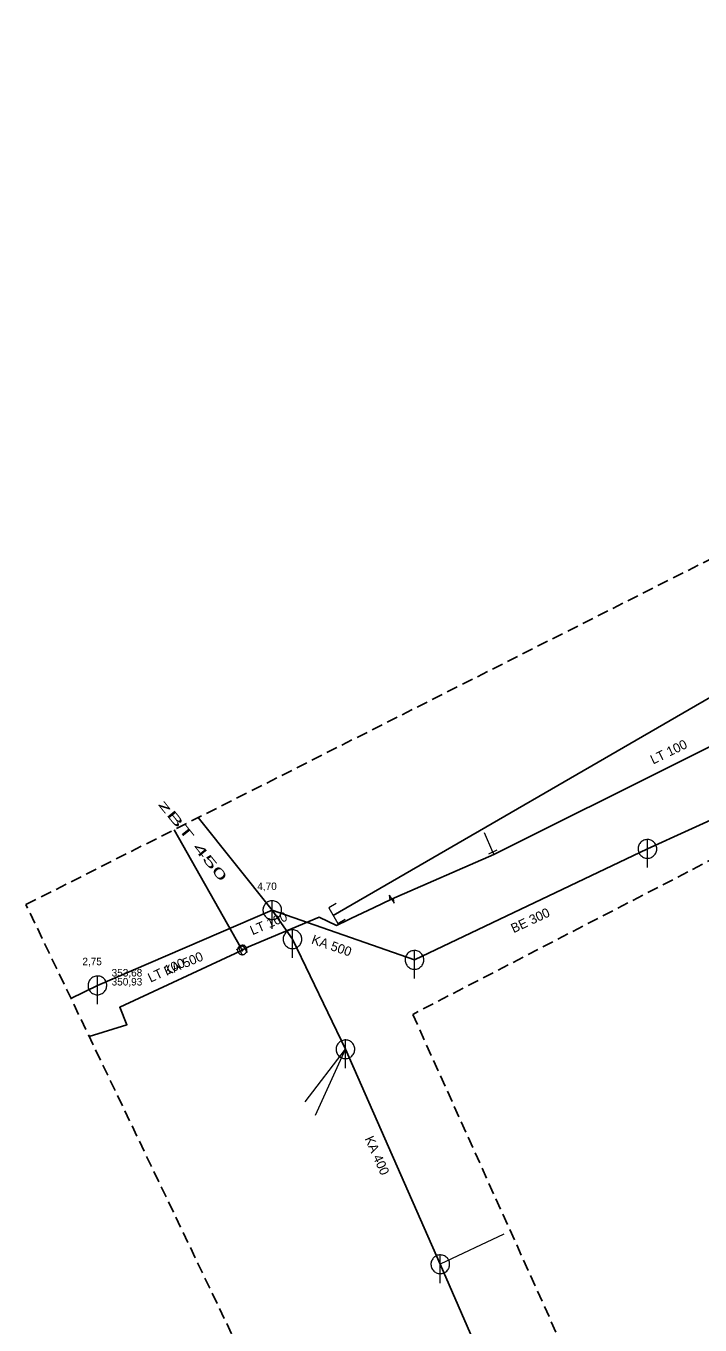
# Model space of a CAD drawing. Extents: x -688691 to -688449, y -974248 to -973966.
# Drawn here: x -688691.4 to -688619.4, y -974104.2 to -973965.6 of the extents above; entities that cross this region are included whole.
import ezdxf

# ---------------------------------------------------------------- set-up
doc = ezdxf.new("R2010")
doc.units = 0
doc.header["$LTSCALE"] = 0.4
doc.linetypes.add('MEDIUM_DASHED', pattern=[4.5, 3, -1.5])
for name, color, linetype, lineweight in [('1', 7, 'MEDIUM_DASHED', 25), ('11', 7, 'Continuous', 13), ('13', 7, 'Continuous', 13), ('14', 7, 'Continuous', 25), ('17', 7, 'Continuous', 25), ('22', 7, 'Continuous', 13), ('31', 7, 'Continuous', 13), ('34', 7, 'Continuous', 13), ('47', 7, 'Continuous', 13)]:
    doc.layers.add(name, color=color, linetype=linetype, lineweight=lineweight)

msp = doc.modelspace()

# ---------------------------------------------------------------- linework, layer by layer
at = {"layer": '1'}
msp.add_lwpolyline([(-688492.642, -974007.422), (-688474.778, -973965.553), (-688449.099, -973975.602), (-688472.545, -974030.309), (-688492.642, -974033.659), (-688555.165, -974021.936), (-688650.066, -974071.061), (-688624.387, -974128.002), (-688613.222, -974120.745), (-688593.125, -974162.055), (-688604.29, -974165.404), (-688581.96, -974212.855), (-688565.213, -974206.156), (-688558.514, -974230.719), (-688607.64, -974248.024), (-688622.154, -974231.277), (-688607.64, -974225.136), (-688626.62, -974194.433), (-688691.376, -974059.338), (-688565.213, -973995.698), (-688544, -974002.397)], close=True, dxfattribs=at)
at = {"layer": '11'}
for p, q in [((-688661.569, -974080.396), (-688657.26, -974074.794)), ((-688660.457, -974081.825), (-688657.26, -974074.794)), ((-688640.344, -974094.539), (-688647.127, -974097.744))]:
    msp.add_line(p, q, dxfattribs=at)
at = {"layer": '13'}
msp.add_line((-688641.528, -974053.762), (-688642.39, -974051.695), dxfattribs=at)
at = {"layer": '14'}
for p, q in [((-688658.556, -974060.52), (-688598.575, -974025.813)), ((-688596.688, -974040.453), (-688625, -974053.399)), ((-688665.07, -974059.94), (-688672.991, -974050.064)), ((-688625, -974053.399), (-688649.879, -974065.25)), ((-688662.91, -974063.039), (-688665.07, -974059.94)), ((-688649.879, -974065.25), (-688665.07, -974059.94)), ((-688657.26, -974074.794), (-688662.91, -974063.039)), ((-688647.127, -974097.744), (-688657.26, -974074.794)), ((-688642.199, -974109.067), (-688647.127, -974097.744))]:
    msp.add_line(p, q, dxfattribs=at)
at = {"layer": '14', "lineweight": 13}
for p, q in [((-688641.528, -974053.762), (-688641.42, -974053.987)), ((-688668.51, -974064.3), (-688668.28, -974064.199)), ((-688668.28, -974064.199), (-688668.449, -974063.89)), ((-688668.28, -974064.199), (-688668.02, -974064.039))]:
    msp.add_line(p, q, dxfattribs=at)
at = {"layer": '14'}
msp.add_lwpolyline([(-688686.573, -974069.357), (-688683.75, -974067.969), (-688665.07, -974059.94)], dxfattribs=at)
at = {"layer": '17'}
msp.add_line((-688668.449, -974063.89), (-688675.546, -974051.353), dxfattribs=at)
for points in [[(-688652.327, -974058.754), (-688641.42, -974053.987), (-688601.114, -974033.895)], [(-688668.02, -974064.039), (-688660.05, -974060.699), (-688658.199, -974061.559), (-688657.05, -974061.01), (-688656.609, -974060.809), (-688654.27, -974059.68), (-688652.327, -974058.754)], [(-688684.625, -974073.422), (-688680.6, -974072.17), (-688681.36, -974070.309), (-688668.51, -974064.3)]]:
    msp.add_lwpolyline(points, dxfattribs=at)
at = {"layer": '22'}
for p, q in [((-688625, -974055.399), (-688624.999, -974052.399)), ((-688665.07, -974061.94), (-688665.069, -974058.94)), ((-688662.91, -974065.04), (-688662.909, -974062.04)), ((-688649.88, -974067.25), (-688649.879, -974064.25)), ((-688683.75, -974069.969), (-688683.749, -974066.969)), ((-688657.26, -974076.794), (-688657.259, -974073.794)), ((-688647.127, -974099.744), (-688647.126, -974096.744))]:
    msp.add_line(p, q, dxfattribs=at)
for points in [[(-688624, -974053.399), (-688624.005, -974053.29), (-688624.023, -974053.182), (-688624.053, -974053.076), (-688624.093, -974052.975), (-688624.145, -974052.878), (-688624.207, -974052.788), (-688624.279, -974052.705), (-688624.359, -974052.631), (-688624.447, -974052.565), (-688624.541, -974052.51), (-688624.641, -974052.465), (-688624.746, -974052.432), (-688624.853, -974052.41), (-688624.962, -974052.4), (-688625.072, -974052.402), (-688625.18, -974052.416), (-688625.287, -974052.441), (-688625.39, -974052.478), (-688625.488, -974052.527), (-688625.58, -974052.585), (-688625.666, -974052.654), (-688625.743, -974052.731), (-688625.812, -974052.817), (-688625.871, -974052.909), (-688625.919, -974053.007), (-688625.956, -974053.11), (-688625.982, -974053.217), (-688625.996, -974053.325), (-688625.999, -974053.435), (-688625.989, -974053.544), (-688625.968, -974053.651), (-688625.934, -974053.755), (-688625.89, -974053.855), (-688625.835, -974053.95), (-688625.769, -974054.038), (-688625.695, -974054.118), (-688625.612, -974054.19), (-688625.522, -974054.252), (-688625.426, -974054.304), (-688625.324, -974054.345), (-688625.219, -974054.375), (-688625.111, -974054.393), (-688625.001, -974054.399), (-688624.892, -974054.393), (-688624.784, -974054.375), (-688624.679, -974054.346), (-688624.577, -974054.305), (-688624.48, -974054.253), (-688624.39, -974054.191), (-688624.307, -974054.12), (-688624.232, -974054.04), (-688624.167, -974053.952), (-688624.111, -974053.858), (-688624.067, -974053.758), (-688624.033, -974053.654), (-688624.011, -974053.546), (-688624.001, -974053.437)], [(-688664.07, -974059.94), (-688664.075, -974059.831), (-688664.093, -974059.723), (-688664.123, -974059.617), (-688664.163, -974059.516), (-688664.215, -974059.419), (-688664.277, -974059.329), (-688664.349, -974059.246), (-688664.429, -974059.172), (-688664.517, -974059.106), (-688664.611, -974059.051), (-688664.711, -974059.006), (-688664.816, -974058.973), (-688664.923, -974058.951), (-688665.032, -974058.941), (-688665.142, -974058.943), (-688665.25, -974058.957), (-688665.357, -974058.982), (-688665.46, -974059.019), (-688665.558, -974059.068), (-688665.65, -974059.126), (-688665.736, -974059.195), (-688665.813, -974059.272), (-688665.882, -974059.358), (-688665.941, -974059.45), (-688665.989, -974059.548), (-688666.026, -974059.651), (-688666.052, -974059.758), (-688666.066, -974059.866), (-688666.069, -974059.976), (-688666.059, -974060.085), (-688666.038, -974060.192), (-688666.004, -974060.296), (-688665.96, -974060.396), (-688665.905, -974060.491), (-688665.839, -974060.579), (-688665.765, -974060.659), (-688665.682, -974060.731), (-688665.592, -974060.793), (-688665.496, -974060.845), (-688665.394, -974060.886), (-688665.289, -974060.916), (-688665.181, -974060.934), (-688665.071, -974060.94), (-688664.962, -974060.934), (-688664.854, -974060.916), (-688664.749, -974060.887), (-688664.647, -974060.846), (-688664.55, -974060.794), (-688664.46, -974060.732), (-688664.377, -974060.661), (-688664.302, -974060.581), (-688664.237, -974060.493), (-688664.181, -974060.399), (-688664.137, -974060.299), (-688664.103, -974060.195), (-688664.081, -974060.087), (-688664.071, -974059.978)], [(-688661.91, -974063.04), (-688661.915, -974062.931), (-688661.933, -974062.823), (-688661.963, -974062.717), (-688662.003, -974062.616), (-688662.055, -974062.519), (-688662.117, -974062.429), (-688662.189, -974062.346), (-688662.269, -974062.272), (-688662.357, -974062.206), (-688662.451, -974062.151), (-688662.551, -974062.106), (-688662.656, -974062.073), (-688662.763, -974062.051), (-688662.872, -974062.041), (-688662.982, -974062.043), (-688663.09, -974062.057), (-688663.197, -974062.082), (-688663.3, -974062.119), (-688663.398, -974062.168), (-688663.49, -974062.226), (-688663.576, -974062.295), (-688663.653, -974062.372), (-688663.722, -974062.458), (-688663.781, -974062.55), (-688663.829, -974062.648), (-688663.866, -974062.751), (-688663.892, -974062.858), (-688663.906, -974062.966), (-688663.909, -974063.076), (-688663.899, -974063.185), (-688663.878, -974063.292), (-688663.844, -974063.396), (-688663.8, -974063.496), (-688663.745, -974063.591), (-688663.679, -974063.679), (-688663.605, -974063.759), (-688663.522, -974063.831), (-688663.432, -974063.893), (-688663.336, -974063.945), (-688663.234, -974063.986), (-688663.129, -974064.016), (-688663.021, -974064.034), (-688662.911, -974064.04), (-688662.802, -974064.034), (-688662.694, -974064.016), (-688662.589, -974063.987), (-688662.487, -974063.946), (-688662.39, -974063.894), (-688662.3, -974063.832), (-688662.217, -974063.761), (-688662.142, -974063.681), (-688662.077, -974063.593), (-688662.021, -974063.499), (-688661.977, -974063.399), (-688661.943, -974063.295), (-688661.921, -974063.187), (-688661.911, -974063.078)], [(-688648.88, -974065.25), (-688648.885, -974065.141), (-688648.903, -974065.033), (-688648.933, -974064.927), (-688648.973, -974064.826), (-688649.025, -974064.729), (-688649.087, -974064.639), (-688649.159, -974064.556), (-688649.239, -974064.482), (-688649.327, -974064.416), (-688649.421, -974064.361), (-688649.521, -974064.316), (-688649.626, -974064.283), (-688649.733, -974064.261), (-688649.842, -974064.251), (-688649.952, -974064.253), (-688650.06, -974064.267), (-688650.167, -974064.292), (-688650.27, -974064.329), (-688650.368, -974064.378), (-688650.46, -974064.436), (-688650.546, -974064.505), (-688650.623, -974064.582), (-688650.692, -974064.668), (-688650.751, -974064.76), (-688650.799, -974064.858), (-688650.836, -974064.961), (-688650.862, -974065.068), (-688650.876, -974065.176), (-688650.879, -974065.286), (-688650.869, -974065.395), (-688650.848, -974065.502), (-688650.814, -974065.606), (-688650.77, -974065.706), (-688650.715, -974065.801), (-688650.649, -974065.889), (-688650.575, -974065.969), (-688650.492, -974066.041), (-688650.402, -974066.103), (-688650.306, -974066.155), (-688650.204, -974066.196), (-688650.099, -974066.226), (-688649.991, -974066.244), (-688649.881, -974066.25), (-688649.772, -974066.244), (-688649.664, -974066.226), (-688649.559, -974066.197), (-688649.457, -974066.156), (-688649.36, -974066.104), (-688649.27, -974066.042), (-688649.187, -974065.971), (-688649.112, -974065.891), (-688649.047, -974065.803), (-688648.991, -974065.709), (-688648.947, -974065.609), (-688648.913, -974065.505), (-688648.891, -974065.397), (-688648.881, -974065.288)], [(-688682.75, -974067.969), (-688682.755, -974067.86), (-688682.773, -974067.752), (-688682.803, -974067.646), (-688682.843, -974067.545), (-688682.895, -974067.448), (-688682.957, -974067.358), (-688683.029, -974067.275), (-688683.109, -974067.201), (-688683.197, -974067.135), (-688683.291, -974067.08), (-688683.391, -974067.035), (-688683.496, -974067.002), (-688683.603, -974066.98), (-688683.712, -974066.97), (-688683.822, -974066.972), (-688683.93, -974066.986), (-688684.037, -974067.011), (-688684.14, -974067.048), (-688684.238, -974067.097), (-688684.33, -974067.155), (-688684.416, -974067.224), (-688684.493, -974067.301), (-688684.562, -974067.387), (-688684.621, -974067.479), (-688684.669, -974067.577), (-688684.706, -974067.68), (-688684.732, -974067.787), (-688684.746, -974067.895), (-688684.749, -974068.005), (-688684.739, -974068.114), (-688684.718, -974068.221), (-688684.684, -974068.325), (-688684.64, -974068.425), (-688684.585, -974068.52), (-688684.519, -974068.608), (-688684.445, -974068.688), (-688684.362, -974068.76), (-688684.272, -974068.822), (-688684.176, -974068.874), (-688684.074, -974068.915), (-688683.969, -974068.945), (-688683.861, -974068.963), (-688683.751, -974068.969), (-688683.642, -974068.963), (-688683.534, -974068.945), (-688683.429, -974068.916), (-688683.327, -974068.875), (-688683.23, -974068.823), (-688683.14, -974068.761), (-688683.057, -974068.69), (-688682.982, -974068.61), (-688682.917, -974068.522), (-688682.861, -974068.428), (-688682.817, -974068.328), (-688682.783, -974068.224), (-688682.761, -974068.116), (-688682.751, -974068.007)], [(-688656.26, -974074.794), (-688656.265, -974074.685), (-688656.283, -974074.577), (-688656.313, -974074.471), (-688656.353, -974074.37), (-688656.405, -974074.273), (-688656.467, -974074.183), (-688656.539, -974074.1), (-688656.619, -974074.026), (-688656.707, -974073.96), (-688656.801, -974073.905), (-688656.901, -974073.86), (-688657.006, -974073.827), (-688657.113, -974073.805), (-688657.222, -974073.795), (-688657.332, -974073.797), (-688657.44, -974073.811), (-688657.547, -974073.836), (-688657.65, -974073.873), (-688657.748, -974073.922), (-688657.84, -974073.98), (-688657.926, -974074.049), (-688658.003, -974074.126), (-688658.072, -974074.212), (-688658.131, -974074.304), (-688658.179, -974074.402), (-688658.216, -974074.505), (-688658.242, -974074.612), (-688658.256, -974074.72), (-688658.259, -974074.83), (-688658.249, -974074.939), (-688658.228, -974075.046), (-688658.194, -974075.15), (-688658.15, -974075.25), (-688658.095, -974075.345), (-688658.029, -974075.433), (-688657.955, -974075.513), (-688657.872, -974075.585), (-688657.782, -974075.647), (-688657.686, -974075.699), (-688657.584, -974075.74), (-688657.479, -974075.77), (-688657.371, -974075.788), (-688657.261, -974075.794), (-688657.152, -974075.788), (-688657.044, -974075.77), (-688656.939, -974075.741), (-688656.837, -974075.7), (-688656.74, -974075.648), (-688656.65, -974075.586), (-688656.567, -974075.515), (-688656.492, -974075.435), (-688656.427, -974075.347), (-688656.371, -974075.253), (-688656.327, -974075.153), (-688656.293, -974075.049), (-688656.271, -974074.941), (-688656.261, -974074.832)], [(-688646.127, -974097.744), (-688646.132, -974097.635), (-688646.15, -974097.527), (-688646.18, -974097.421), (-688646.22, -974097.32), (-688646.272, -974097.223), (-688646.334, -974097.133), (-688646.406, -974097.05), (-688646.486, -974096.976), (-688646.574, -974096.91), (-688646.668, -974096.855), (-688646.768, -974096.81), (-688646.873, -974096.777), (-688646.98, -974096.755), (-688647.089, -974096.745), (-688647.199, -974096.747), (-688647.307, -974096.761), (-688647.414, -974096.786), (-688647.517, -974096.823), (-688647.615, -974096.872), (-688647.707, -974096.93), (-688647.793, -974096.999), (-688647.87, -974097.076), (-688647.939, -974097.162), (-688647.998, -974097.254), (-688648.046, -974097.352), (-688648.083, -974097.455), (-688648.109, -974097.562), (-688648.123, -974097.67), (-688648.126, -974097.78), (-688648.116, -974097.889), (-688648.095, -974097.996), (-688648.061, -974098.1), (-688648.017, -974098.2), (-688647.962, -974098.295), (-688647.896, -974098.383), (-688647.822, -974098.463), (-688647.739, -974098.535), (-688647.649, -974098.597), (-688647.553, -974098.649), (-688647.451, -974098.69), (-688647.346, -974098.72), (-688647.238, -974098.738), (-688647.128, -974098.744), (-688647.019, -974098.738), (-688646.911, -974098.72), (-688646.806, -974098.691), (-688646.704, -974098.65), (-688646.607, -974098.598), (-688646.517, -974098.536), (-688646.434, -974098.465), (-688646.359, -974098.385), (-688646.294, -974098.297), (-688646.238, -974098.203), (-688646.194, -974098.103), (-688646.16, -974097.999), (-688646.138, -974097.891), (-688646.128, -974097.782)]]:
    msp.add_lwpolyline(points, close=True, dxfattribs=at)
at = {"layer": '31'}
msp.add_lwpolyline([(-688658.26, -974059.232), (-688659.04, -974059.684), (-688658.072, -974061.356), (-688657.292, -974060.905)], dxfattribs=at)
at = {"layer": '34'}
for p, q in [((-688641.077, -974053.545), (-688641.979, -974053.977)), ((-688668.887, -974064.13), (-688668.01, -974063.65)), ((-688668.722, -974063.847), (-688668.298, -974064.753)), ((-688668.282, -974063.613), (-688667.758, -974064.465))]:
    msp.add_line(p, q, dxfattribs=at)
at = {"layer": '47'}
msp.add_line((-688652.603, -974058.326), (-688652.513, -974058.828), dxfattribs=at)
msp.add_lwpolyline([(-688652.603, -974058.326), (-688652.05, -974059.181), (-688652.14, -974058.679)], dxfattribs=at)
for points in [[(-688667.821, -974063.999), (-688667.844, -974063.953), (-688667.873, -974063.908), (-688667.905, -974063.868), (-688667.941, -974063.83), (-688667.982, -974063.797), (-688668.026, -974063.768), (-688668.072, -974063.744), (-688668.121, -974063.725), (-688668.171, -974063.711), (-688668.223, -974063.702), (-688668.276, -974063.698), (-688668.328, -974063.701), (-688668.379, -974063.709), (-688668.43, -974063.722), (-688668.479, -974063.74), (-688668.525, -974063.763), (-688668.57, -974063.792), (-688668.611, -974063.825), (-688668.648, -974063.86), (-688668.681, -974063.901), (-688668.71, -974063.945), (-688668.735, -974063.992), (-688668.754, -974064.041), (-688668.768, -974064.09), (-688668.776, -974064.142), (-688668.78, -974064.195), (-688668.777, -974064.247), (-688668.769, -974064.298), (-688668.756, -974064.349), (-688668.738, -974064.398), (-688668.715, -974064.444), (-688668.686, -974064.489), (-688668.654, -974064.53), (-688668.618, -974064.567), (-688668.577, -974064.6), (-688668.534, -974064.63), (-688668.487, -974064.654), (-688668.438, -974064.673), (-688668.388, -974064.687), (-688668.336, -974064.695), (-688668.283, -974064.699), (-688668.232, -974064.697), (-688668.18, -974064.688), (-688668.129, -974064.675), (-688668.08, -974064.657), (-688668.034, -974064.634), (-688667.989, -974064.605), (-688667.948, -974064.574), (-688667.911, -974064.537), (-688667.878, -974064.496), (-688667.848, -974064.453), (-688667.825, -974064.406), (-688667.806, -974064.358), (-688667.792, -974064.307), (-688667.783, -974064.255), (-688667.779, -974064.202), (-688667.782, -974064.151), (-688667.79, -974064.099), (-688667.803, -974064.048)], [(-688668.204, -974064.166), (-688668.208, -974064.158), (-688668.213, -974064.151), (-688668.218, -974064.144), (-688668.224, -974064.138), (-688668.231, -974064.133), (-688668.238, -974064.128), (-688668.245, -974064.124), (-688668.253, -974064.121), (-688668.262, -974064.119), (-688668.27, -974064.117), (-688668.279, -974064.117), (-688668.288, -974064.117), (-688668.296, -974064.118), (-688668.304, -974064.12), (-688668.312, -974064.123), (-688668.32, -974064.127), (-688668.327, -974064.132), (-688668.334, -974064.137), (-688668.34, -974064.143), (-688668.345, -974064.15), (-688668.35, -974064.157), (-688668.354, -974064.164), (-688668.357, -974064.172), (-688668.36, -974064.181), (-688668.361, -974064.189), (-688668.361, -974064.198), (-688668.361, -974064.207), (-688668.36, -974064.215), (-688668.358, -974064.223), (-688668.355, -974064.231), (-688668.351, -974064.239), (-688668.346, -974064.246), (-688668.341, -974064.253), (-688668.335, -974064.259), (-688668.328, -974064.264), (-688668.322, -974064.269), (-688668.314, -974064.273), (-688668.306, -974064.276), (-688668.297, -974064.279), (-688668.289, -974064.28), (-688668.28, -974064.28), (-688668.271, -974064.28), (-688668.263, -974064.279), (-688668.255, -974064.277), (-688668.247, -974064.274), (-688668.239, -974064.27), (-688668.232, -974064.265), (-688668.225, -974064.26), (-688668.219, -974064.254), (-688668.214, -974064.247), (-688668.209, -974064.241), (-688668.205, -974064.233), (-688668.202, -974064.225), (-688668.2, -974064.216), (-688668.198, -974064.208), (-688668.198, -974064.199), (-688668.198, -974064.19), (-688668.199, -974064.182), (-688668.201, -974064.174)]]:
    msp.add_lwpolyline(points, close=True, dxfattribs=at)

# ---------------------------------------------------------------- texts
at = {"layer": '1'}
for s, rotation, p in [('LT 100', 26, (-688624.39, -974044.397)), ('LT 100', 23, (-688667.182, -974062.62)), ('BE 300', 25, (-688639.294, -974062.406)), ('KA 500', 341, (-688660.961, -974063.479)), ('KA 500', 23, (-688676.381, -974066.963)), ('LT 100', 25, (-688678.069, -974067.682)), ('KA 400', 294, (-688655.221, -974084.326))]:
    msp.add_text(s, height=1, rotation=rotation, dxfattribs=at).set_placement(p)
at = {"layer": '1', "width": 2.15}
msp.add_text('zBT 450 ', height=1, rotation=309, dxfattribs=at).set_placement((-688677.328, -974048.643))
at = {"layer": '1'}
for s, p in [('4,70', (-688666.67, -974057.787)), ('2,75', (-688685.35, -974065.817))]:
    msp.add_text(s, height=0.8, dxfattribs=at).set_placement(p)
at = {"layer": '22'}
for s, p in [('353,68', (-688682.228, -974067.021)), ('350,93', (-688682.228, -974067.981))]:
    msp.add_text(s, height=0.8, dxfattribs=at).set_placement(p)

doc.saveas('drawing.dxf')
